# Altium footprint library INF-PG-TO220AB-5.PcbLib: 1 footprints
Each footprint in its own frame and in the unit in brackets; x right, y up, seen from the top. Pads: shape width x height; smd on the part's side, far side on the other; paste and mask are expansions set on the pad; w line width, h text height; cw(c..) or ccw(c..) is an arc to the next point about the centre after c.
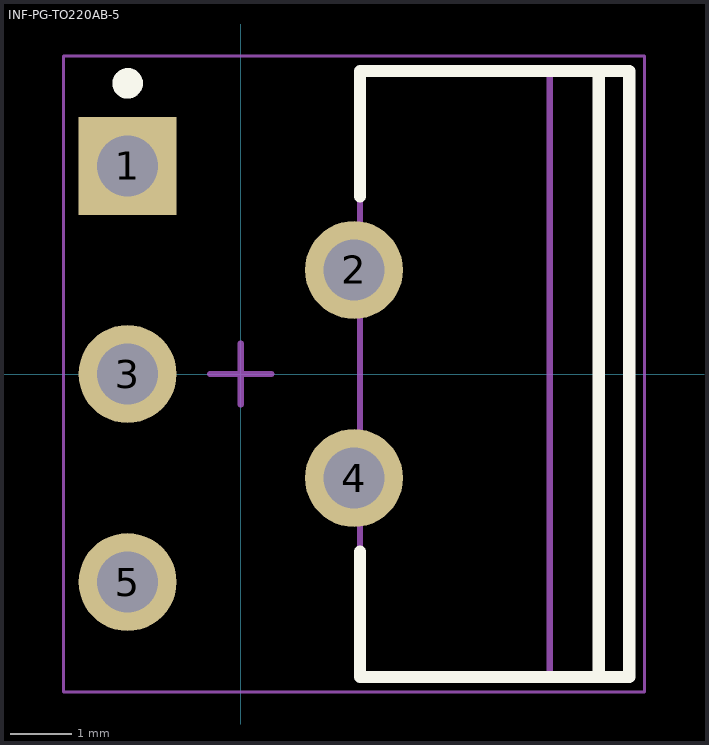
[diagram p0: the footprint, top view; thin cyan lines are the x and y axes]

## INF-PG-TO220AB-5 [mm] "FM, 5-Leads, Body 9.9x4.4mm, Pitch 1.7mm"
height 21.2
pads (5):
  rect 1.6x1.6 hole 1: 1(-1.85,3.4)
  round 1.6 hole 1: 2(1.85,1.7) 3(-1.85,0) 4(1.85,-1.7) 5(-1.85,-3.4)
Top Overlay:
  circle w0.25: c-1.85,4.75 r0.125
  lines w0.2: 1.95,-2.9 1.95,-4.95 6.35,-4.95 6.35,4.95 1.95,4.95 1.95,2.9 ; 5.85,-4.95 5.85,4.95
Mechanical 13:
  lines w0.1: 5.05,-4.95 5.05,4.95 ; 1.95,-4.95 6.35,-4.95 6.35,4.95 1.95,4.95 1.95,-4.95
Mechanical 15:
  lines w0.05: -2.9,-5.2 6.6,-5.2 6.6,5.2 -2.9,5.2 -2.9,-5.2
  lines w0.1: -0.5,0 0.5,0 ; 0,-0.5 0,0.5
3D body: height 21.2, standoff 20.25, extent 5.05,-4.95 6.35,4.95
3D body: height 18.77, standoff 18.4, extent 5.05,-4.95 6.35,-1.85
3D body: height 18.77, standoff 18.4, extent 5.05,1.85 6.35,4.95
3D body: height 18.4, standoff 18.04, extent 5.05,-4.95 6.35,-1.85
3D body: height 18.4, standoff 18.04, extent 5.05,1.85 6.35,4.95
3D body: height 19.11, standoff 18.76, extent 5.05,-4.95 6.35,-1.814
3D body: height 19.11, standoff 18.76, extent 5.05,1.814 6.35,4.95
3D body: height 18.04, standoff 17.69, extent 5.05,-4.95 6.35,-1.814
3D body: height 18.04, standoff 17.69, extent 5.05,1.814 6.35,4.95
3D body: height 19.43, standoff 19.11, extent 5.05,-4.95 6.35,-1.709
3D body: height 19.43, standoff 19.11, extent 5.05,1.709 6.35,4.95
3D body: height 17.7, standoff 17.37, extent 5.05,-4.95 6.35,-1.709
3D body: height 17.7, standoff 17.37, extent 5.05,1.709 6.35,4.95
3D body: height 19.71, standoff 19.43, extent 5.05,-4.95 6.35,-1.538
3D body: height 19.71, standoff 19.43, extent 5.05,1.538 6.35,4.95
3D body: height 17.38, standoff 17.09, extent 5.05,-4.95 6.35,-1.538
3D body: height 17.38, standoff 17.09, extent 5.05,1.538 6.35,4.95
3D body: height 19.94, standoff 19.71, extent 5.05,-4.95 6.35,-1.308
3D body: height 19.94, standoff 19.71, extent 5.05,1.308 6.35,4.95
3D body: height 17.1, standoff 16.86, extent 5.05,-4.95 6.35,-1.308
3D body: height 17.1, standoff 16.86, extent 5.05,1.308 6.35,4.95
3D body: height 20.11, standoff 19.94, extent 5.05,-4.95 6.35,-1.028
3D body: height 20.11, standoff 19.94, extent 5.05,1.028 6.35,4.95
3D body: height 16.87, standoff 16.69, extent 5.05,-4.95 6.35,-1.028
3D body: height 16.87, standoff 16.69, extent 5.05,1.028 6.35,4.95
3D body: height 20.22, standoff 20.11, extent 5.05,-4.95 6.35,-0.708
3D body: height 20.22, standoff 20.11, extent 5.05,0.708 6.35,4.95
3D body: height 16.7, standoff 16.59, extent 5.05,-4.95 6.35,-0.708
3D body: height 16.7, standoff 16.59, extent 5.05,0.708 6.35,4.95
3D body: height 20.25, standoff 20.21, extent 5.05,-4.95 6.35,-0.361
3D body: height 20.25, standoff 20.21, extent 5.05,0.361 6.35,4.95
3D body: height 16.59, standoff 16.55, extent 5.05,-4.95 6.35,-0.361
3D body: height 16.59, standoff 16.55, extent 5.05,0.361 6.35,4.95
3D body: height 16.55, standoff 14.8, extent 5.05,-4.95 6.35,4.95
3D body: height 14.8, standoff 9.75, extent 1.95,-4.95 6.35,4.95
3D body: height 0, standoff -1.6, extent -2.1,-3.8 -1.6,-3
3D body: height 9.75, standoff 5.13, extent 3.9,-3.95 4.4,-2.85
3D body: height 5.13, standoff 4.63, extent -2.1,-3.95 4.4,-2.85
3D body: height 4.63, standoff 0, extent -2.1,-3.95 -1.6,-2.85
3D body: height 0, standoff -1.6, extent 1.6,-2.1 2.1,-1.3
3D body: height 9.75, standoff 5.13, extent 3.9,-2.25 4.4,-1.15
3D body: height 5.13, standoff 4.63, extent 1.6,-2.25 4.4,-1.15
3D body: height 4.63, standoff 0, extent 1.6,-2.25 2.1,-1.15
3D body: height 0, standoff -1.6, extent -2.1,-0.4 -1.6,0.4
3D body: height 9.75, standoff 5.13, extent 3.9,-0.55 4.4,0.55
3D body: height 5.13, standoff 4.63, extent -2.1,-0.55 4.4,0.55
3D body: height 4.63, standoff 0, extent -2.1,-0.55 -1.6,0.55
3D body: height 0, standoff -1.6, extent 1.6,1.3 2.1,2.1
3D body: height 9.75, standoff 5.13, extent 3.9,1.15 4.4,2.25
3D body: height 5.13, standoff 4.63, extent 1.6,1.15 4.4,2.25
3D body: height 4.63, standoff 0, extent 1.6,1.15 2.1,2.25
3D body: height 0, standoff -1.6, extent -2.1,3 -1.6,3.8
3D body: height 9.75, standoff 5.13, extent 3.9,2.85 4.4,3.95
3D body: height 5.13, standoff 4.63, extent -2.1,2.85 4.4,3.95
3D body: height 4.63, standoff 0, extent -2.1,2.85 -1.6,3.95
